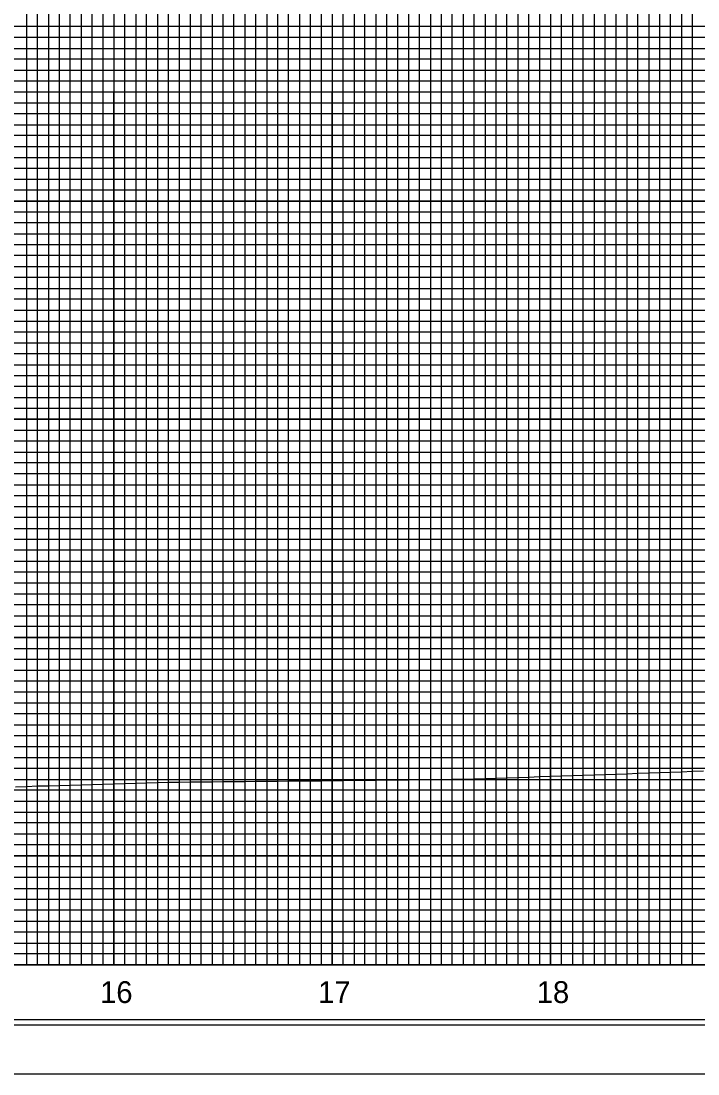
# Model space of a CAD drawing. Extents: x 2345490 to 2445302, y 465165 to 573888.
# Drawn here: x 2382324.3 to 2382634.3, y 515087.5 to 515570 of the extents above; entities that cross this region are included whole.
import ezdxf

# ---------------------------------------------------------------- set-up
doc = ezdxf.new("R2010")
doc.units = 0
for name, color, linetype in [('Old_Level_1', 7, 'Continuous'), ('Old_Level_18', 7, 'Continuous'), ('Old_Level_41', 7, 'Continuous'), ('Old_Level_42', 7, 'Continuous'), ('Old_Level_43', 7, 'Continuous'), ('Old_Level_50', 7, 'Continuous'), ('Old_Level_51', 7, 'Continuous'), ('Old_Level_57', 7, 'Continuous'), ('Old_Level_62', 7, 'Continuous'), ('Old_Level_63', 7, 'Continuous')]:
    doc.layers.add(name, color=color, linetype=linetype)

msp = doc.modelspace()

# ---------------------------------------------------------------- linework, layer by layer
at = {"layer": 'Old_Level_1'}
msp.add_lwpolyline([(2382321.799, 515219.106), (2382326.799, 515219.315), (2382331.799, 515219.48325), (2382336.799, 515219.63125), (2382341.799, 515219.77925), (2382346.799, 515219.9275), (2382351.799, 515220.0755), (2382356.799, 515220.2235), (2382361.799, 515220.37025), (2382366.799, 515220.51825), (2382371.799, 515220.66625), (2382376.799, 515220.8145), (2382381.799, 515220.9625), (2382386.799, 515221.1105), (2382391.799, 515221.2585), (2382396.799, 515221.3125), (2382401.799, 515221.35825), (2382406.799, 515221.404), (2382411.799, 515221.44975), (2382416.799, 515221.4955), (2382421.799, 515221.54125), (2382426.799, 515221.591), (2382431.799, 515221.63725), (2382436.799, 515221.68325), (2382441.799, 515221.72925), (2382446.799, 515221.77525), (2382451.799, 515221.82125), (2382456.799, 515221.86725), (2382461.799, 515221.91325), (2382466.799, 515221.969), (2382471.799, 515222.02575), (2382476.799, 515222.08225), (2382481.799, 515222.139), (2382486.799, 515222.19575), (2382491.799, 515222.25225), (2382496.799, 515222.3085), (2382501.799, 515222.36525), (2382506.799, 515222.42175), (2382511.799, 515222.4785), (2382516.799, 515222.535), (2382521.799, 515222.59175), (2382526.799, 515222.648), (2382531.799, 515222.7645), (2382536.799, 515222.931), (2382541.799, 515223.0975), (2382546.799, 515223.264), (2382551.799, 515223.4305), (2382556.799, 515223.59725), (2382561.799, 515223.759), (2382566.799, 515223.92575), (2382571.799, 515224.0925), (2382576.799, 515224.25925), (2382581.799, 515224.42625), (2382586.799, 515224.593), (2382591.799, 515224.75675), (2382596.799, 515224.92375), (2382601.799, 515225.09925), (2382606.799, 515225.28625), (2382611.799, 515225.47325), (2382616.799, 515225.66025), (2382621.799, 515225.8475), (2382626.799, 515226.0345), (2382631.799, 515226.22325), (2382636.799, 515226.41025)], dxfattribs=at)
at = {"layer": 'Old_Level_18'}
msp.add_lwpolyline([(2383216.79875, 516162.5265), (2381716.79875, 516162.5265), (2381716.79875, 515112.5265), (2383216.79875, 515112.5265)], close=True, dxfattribs=at)
at = {"layer": 'Old_Level_41'}
msp.add_line((2383216.79875, 515137.5265), (2381716.79875, 515137.5265), dxfattribs=at)
for points in [[(2382341.79875, 516162.5265), (2382341.79875, 515137.5265), (2382391.79875, 515137.5265), (2382391.79875, 516162.5265)], [(2382366.79875, 516162.5265), (2382366.79875, 515137.5265), (2382416.79875, 515137.5265), (2382416.79875, 516162.5265)], [(2382441.79875, 516162.5265), (2382441.79875, 515137.5265), (2382491.79875, 515137.5265), (2382491.79875, 516162.5265)], [(2382466.79875, 516162.5265), (2382466.79875, 515137.5265), (2382516.79875, 515137.5265), (2382516.79875, 516162.5265)], [(2382541.79875, 516162.5265), (2382541.79875, 515137.5265), (2382591.79875, 515137.5265), (2382591.79875, 516162.5265)], [(2382566.79875, 516162.5265), (2382566.79875, 515137.5265), (2382616.79875, 515137.5265), (2382616.79875, 516162.5265)], [(2383216.79875, 515562.5265), (2381716.79875, 515562.5265), (2381716.79875, 515512.5265), (2383216.79875, 515512.5265)], [(2383216.79875, 515487.5265), (2381716.79875, 515487.5265), (2381716.79875, 515537.5265), (2383216.79875, 515537.5265)], [(2383216.79875, 515462.5265), (2381716.79875, 515462.5265), (2381716.79875, 515412.5265), (2383216.79875, 515412.5265)], [(2383216.79875, 515387.5265), (2381716.79875, 515387.5265), (2381716.79875, 515437.5265), (2383216.79875, 515437.5265)], [(2383216.79875, 515362.5265), (2381716.79875, 515362.5265), (2381716.79875, 515312.5265), (2383216.79875, 515312.5265)], [(2383216.79875, 515262.5265), (2381716.79875, 515262.5265), (2381716.79875, 515212.5265), (2383216.79875, 515212.5265)], [(2383216.79875, 515187.5265), (2381716.79875, 515187.5265), (2381716.79875, 515237.5265), (2383216.79875, 515237.5265)], [(2383216.79875, 515162.5265), (2381716.79875, 515162.5265)]]:
    msp.add_lwpolyline(points, dxfattribs=at)
at = {"layer": 'Old_Level_42'}
msp.add_lwpolyline([(2383216.79875, 515287.5265), (2381716.79875, 515287.5265), (2381716.79875, 515337.5265), (2383216.79875, 515337.5265)], dxfattribs=at)
at = {"layer": 'Old_Level_43'}
for points in [[(2382326.79875, 516162.5265), (2382326.79875, 515137.5265), (2382326.79875, 515137.5265), (2382331.79875, 515137.5265), (2382331.79875, 516162.5265)], [(2382336.79875, 516162.5265), (2382336.79875, 515137.5265), (2382346.79875, 515137.5265), (2382346.79875, 516162.5265)], [(2382351.79875, 516162.5265), (2382351.79875, 515137.5265), (2382356.79875, 515137.5265), (2382356.79875, 516162.5265)], [(2382361.79875, 516162.5265), (2382361.79875, 515137.5265), (2382371.79875, 515137.5265), (2382371.79875, 516162.5265)], [(2382376.79875, 516162.5265), (2382376.79875, 515137.5265), (2382381.79875, 515137.5265), (2382381.79875, 516162.5265)], [(2382386.79875, 516162.5265), (2382386.79875, 515137.5265), (2382396.79875, 515137.5265), (2382396.79875, 516162.5265)], [(2382401.79875, 516162.5265), (2382401.79875, 515137.5265), (2382406.79875, 515137.5265), (2382406.79875, 516162.5265)], [(2382411.79875, 516162.5265), (2382411.79875, 515137.5265), (2382421.79875, 515137.5265), (2382421.79875, 516162.5265)], [(2382426.79875, 516162.5265), (2382426.79875, 515137.5265), (2382431.79875, 515137.5265), (2382431.79875, 516162.5265)], [(2382436.79875, 516162.5265), (2382436.79875, 515137.5265), (2382446.79875, 515137.5265), (2382446.79875, 516162.5265)], [(2382451.79875, 516162.5265), (2382451.79875, 515137.5265), (2382456.79875, 515137.5265), (2382456.79875, 516162.5265)], [(2382461.79875, 516162.5265), (2382461.79875, 515137.5265), (2382471.79875, 515137.5265), (2382471.79875, 516162.5265)], [(2382476.79875, 516162.5265), (2382476.79875, 515137.5265)], [(2382476.79875, 515137.5265), (2382481.79875, 515137.5265), (2382481.79875, 516161.9265)], [(2382486.79875, 516161.9265), (2382486.79875, 515137.5265), (2382496.79875, 515137.5265), (2382496.79875, 516162.5265)], [(2382501.79875, 516162.5265), (2382501.79875, 515137.5265), (2382506.79875, 515137.5265), (2382506.79875, 516162.5265)], [(2382511.79875, 516162.5265), (2382511.79875, 515137.5265), (2382521.79875, 515137.5265), (2382521.79875, 516162.5265)], [(2382526.79875, 516162.5265), (2382526.79875, 515137.5265), (2382531.79875, 515137.5265), (2382531.79875, 516162.5265)], [(2382536.79875, 516162.5265), (2382536.79875, 515137.5265), (2382546.79875, 515137.5265), (2382546.79875, 516162.5265)], [(2382551.79875, 516162.5265), (2382551.79875, 515137.5265), (2382556.79875, 515137.5265), (2382556.79875, 516162.5265)], [(2382561.79875, 516162.5265), (2382561.79875, 515137.5265), (2382571.79875, 515137.5265), (2382571.79875, 516162.5265)], [(2382576.79875, 516162.5265), (2382576.79875, 515137.5265), (2382581.79875, 515137.5265), (2382581.79875, 516162.5265)], [(2382586.79875, 516162.5265), (2382586.79875, 515137.5265), (2382596.79875, 515137.5265), (2382596.79875, 516162.5265)], [(2382601.79875, 516162.5265), (2382601.79875, 515137.5265), (2382606.79875, 515137.5265), (2382606.79875, 516162.5265)], [(2382611.79875, 516162.5265), (2382611.79875, 515137.5265), (2382621.79875, 515137.5265), (2382621.79875, 516162.5265)], [(2382626.79875, 516162.5265), (2382626.79875, 515137.5265), (2382631.79875, 515137.5265), (2382631.79875, 516162.5265)], [(2383166.79875, 515567.5265), (2381766.79875, 515567.5265), (2381766.79875, 515557.5265), (2383166.79875, 515557.5265)], [(2383166.79875, 515552.5265), (2381766.79875, 515552.5265), (2381766.79875, 515547.5265), (2383166.79875, 515547.5265)], [(2383166.79875, 515542.5265), (2381766.79875, 515542.5265), (2381766.79875, 515532.5265), (2383166.79875, 515532.5265)], [(2383166.79875, 515527.5265), (2381766.79875, 515527.5265), (2381766.79875, 515522.5265), (2383166.79875, 515522.5265)], [(2383166.79875, 515517.5265), (2381766.79875, 515517.5265), (2381766.79875, 515507.5265), (2383166.79875, 515507.5265)], [(2383166.79875, 515502.5265), (2381766.79875, 515502.5265), (2381766.79875, 515497.5265), (2383166.79875, 515497.5265)], [(2383166.79875, 515492.5265), (2381766.79875, 515492.5265), (2381766.79875, 515482.5265), (2383166.79875, 515482.5265)], [(2383166.79875, 515477.5265), (2381766.79875, 515477.5265), (2381766.79875, 515472.5265), (2383166.79875, 515472.5265)], [(2383166.79875, 515467.5265), (2381766.79875, 515467.5265), (2381766.79875, 515457.5265), (2383166.79875, 515457.5265)], [(2383166.79875, 515452.5265), (2381766.79875, 515452.5265), (2381766.79875, 515447.5265), (2383166.79875, 515447.5265)], [(2383166.79875, 515442.5265), (2381766.79875, 515442.5265), (2381766.79875, 515432.5265), (2383166.79875, 515432.5265)], [(2383166.79875, 515427.5265), (2381766.79875, 515427.5265), (2381766.79875, 515422.5265), (2383166.79875, 515422.5265)], [(2383166.79875, 515417.5265), (2381766.79875, 515417.5265), (2381766.79875, 515407.5265), (2383166.79875, 515407.5265)], [(2383166.79875, 515402.5265), (2381766.79875, 515402.5265), (2381766.79875, 515397.5265), (2383166.79875, 515397.5265)], [(2383166.79875, 515392.5265), (2381766.79875, 515392.5265), (2381766.79875, 515382.5265), (2383166.79875, 515382.5265)], [(2383166.79875, 515377.5265), (2381766.79875, 515377.5265), (2381766.79875, 515372.5265), (2383166.79875, 515372.5265)], [(2383166.79875, 515367.5265), (2381766.79875, 515367.5265), (2381766.79875, 515357.5265), (2383166.79875, 515357.5265)], [(2383166.79875, 515352.5265), (2381766.79875, 515352.5265), (2381766.79875, 515347.5265), (2383166.79875, 515347.5265)], [(2383166.79875, 515342.5265), (2381766.79875, 515342.5265)], [(2381766.79875, 515332.5265), (2383166.79875, 515332.5265)], [(2383166.79875, 515327.5265), (2381766.79875, 515327.5265), (2381766.79875, 515322.5265), (2383166.79875, 515322.5265)], [(2383166.79875, 515317.5265), (2381766.79875, 515317.5265)], [(2381766.79875, 515307.5265), (2383166.79875, 515307.5265)], [(2383166.79875, 515302.5265), (2381766.79875, 515302.5265), (2381766.79875, 515297.5265), (2383166.79875, 515297.5265)], [(2383166.79875, 515292.5265), (2381766.79875, 515292.5265), (2381766.79875, 515282.5265), (2383166.79875, 515282.5265)], [(2383166.79875, 515277.5265), (2381766.79875, 515277.5265), (2381766.79875, 515272.5265), (2383166.79875, 515272.5265)], [(2383166.79875, 515267.5265), (2381766.79875, 515267.5265), (2381766.79875, 515257.5265), (2383166.79875, 515257.5265)], [(2383166.79875, 515252.5265), (2381766.79875, 515252.5265), (2381766.79875, 515247.5265), (2383166.79875, 515247.5265)], [(2383166.79875, 515242.5265), (2381766.79875, 515242.5265), (2381766.79875, 515232.5265), (2383166.79875, 515232.5265)], [(2383166.79875, 515227.5265), (2381766.79875, 515227.5265), (2381766.79875, 515222.5265), (2383166.79875, 515222.5265)], [(2383166.79875, 515217.5265), (2381766.79875, 515217.5265), (2381766.79875, 515207.5265), (2383166.79875, 515207.5265)], [(2383166.79875, 515202.5265), (2381766.79875, 515202.5265), (2381766.79875, 515197.5265), (2383166.79875, 515197.5265)], [(2383166.79875, 515192.5265), (2381766.79875, 515192.5265), (2381766.79875, 515182.5265), (2383166.79875, 515182.5265)], [(2383166.79875, 515177.5265), (2381766.79875, 515177.5265), (2381766.79875, 515172.5265), (2383166.79875, 515172.5265)], [(2383166.79875, 515167.5265), (2381766.79875, 515167.5265), (2381766.79875, 515157.5265), (2383166.79875, 515157.5265)], [(2383166.79875, 515152.5265), (2381766.79875, 515152.5265), (2381766.79875, 515147.5265), (2383166.79875, 515147.5265)], [(2383166.79875, 515142.5265), (2381766.79875, 515142.5265)]]:
    msp.add_lwpolyline(points, dxfattribs=at)
at = {"layer": 'Old_Level_50'}
msp.add_lwpolyline([(2383229.29875, 516165.0765), (2381562.79875, 516165.0765), (2381562.79875, 515109.9765), (2383229.29875, 515109.9765)], close=True, dxfattribs=at)
at = {"layer": 'Old_Level_51'}
msp.add_lwpolyline([(2383233.79875, 516187.5265), (2381549.79875, 516187.5265), (2381549.79875, 515087.5265), (2383233.79875, 515087.5265)], close=True, dxfattribs=at)
at = {"layer": 'Old_Level_57'}
for p, q in [((2381716.79925, 515537.52675), (2386366.79875, 515537.52675)), ((2382366.79875, 515137.52675), (2382366.79875, 515537.52675)), ((2382366.79875, 515137.62675), (2382366.79875, 515537.52675)), ((2382466.79875, 515137.52675), (2382466.79875, 515537.52675)), ((2382466.79875, 515137.62675), (2382466.79875, 515537.52675)), ((2382566.79875, 515137.52675), (2382566.79875, 515537.52675)), ((2382566.79875, 515137.62675), (2382566.79875, 515537.52675)), ((2381716.79925, 515487.52675), (2386366.79875, 515487.52675)), ((2381716.79925, 515437.52675), (2386366.79875, 515437.52675)), ((2381716.79925, 515387.52675), (2386366.79875, 515387.52675)), ((2381716.79925, 515337.52675), (2386366.79875, 515337.52675)), ((2381716.79925, 515287.52675), (2386366.79875, 515287.52675)), ((2381716.79925, 515237.52675), (2386366.79875, 515237.52675)), ((2381716.799, 515187.52675), (2386366.79875, 515187.52675)), ((2381716.79925, 515137.52675), (2386366.79875, 515137.52675))]:
    msp.add_line(p, q, dxfattribs=at)
at = {"layer": 'Old_Level_63'}
msp.add_line((2381766.79875, 515137.5265), (2386228.05125, 515137.5265), dxfattribs=at)

# ---------------------------------------------------------------- texts
at = {"layer": 'Old_Level_62'}
for s, p in [('16', (2382360.481, 515120.0265)), ('17', (2382460.3385, 515120.0265)), ('18', (2382560.46425, 515120.0265))]:
    msp.add_text(s, height=10.000001, dxfattribs=at).set_placement(p)

doc.saveas('drawing.dxf')
